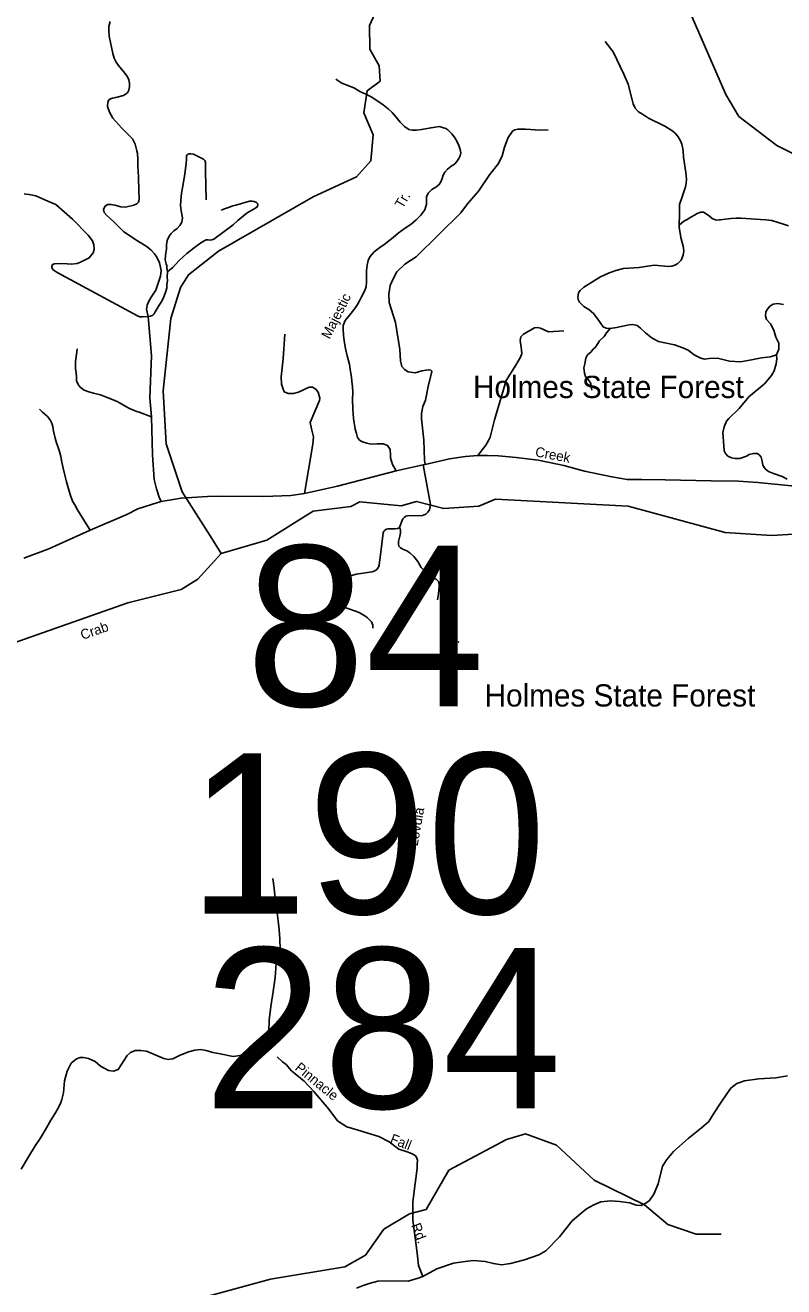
# Model space of a CAD drawing. Extents: x 884530 to 1028605, y 526725 to 653634.
# Drawn here: x 927736 to 932778, y 556470 to 564854 of the extents above; entities that cross this region are included whole.
import ezdxf

# ---------------------------------------------------------------- set-up
doc = ezdxf.new("R2010")
doc.units = 0
for name, color, linetype in [('Exist Boundary Land Use Park Urban CELL', 7, 'Continuous'), ('Exist Hydrographic Creek Single Shore', 7, 'Continuous'), ('Exist Hydrographic Creek Single Shore Label', 7, 'Continuous'), ('Exist Hydrographic Misc Water Feature', 7, 'Continuous'), ('Exist Road Non-System Type 51', 7, 'Continuous'), ('Exist Road Non-System Type 51 Label', 7, 'Continuous'), ('Exist Road Secondary Structure Standard Bridge Number Label', 7, 'Continuous'), ('Exist Road Secondary Type 51 Attributed', 7, 'Continuous'), ('Exist Road Secondary Type 51 Label', 7, 'Continuous')]:
    doc.layers.add(name, color=color, linetype=linetype)

msp = doc.modelspace()

# ---------------------------------------------------------------- linework, layer by layer
at = {"layer": 'Exist Hydrographic Creek Single Shore'}
for points in [[(929039.2, 561344.2), (928965.5, 561460), (928778.8, 561753.2), (928673.5, 562073.5), (928652.7, 562425.1), (928703.3, 562906.5), (928769.1, 563112), (928822.3, 563196.2), (929019.6, 563353), (929649.6, 563714.4), (929938, 563846.4), (930033.4, 563952.8), (930048, 564126.4), (929986.6, 564272.1), (930008.3, 564419.3), (930094.1, 564483.3), (930089.5, 564585.1), (930026.6, 564694.6), (930024.1, 564852.2), (930214.1, 565271.7)], [(929039.2, 561344.2), (929342.7, 561433.3), (929649.7, 561624.1), (929900.9, 561655.1), (929960.4, 561686.7), (930234.7, 561661.4), (930335.8, 561689), (930517.6, 561642.7), (930751.5, 561657.6), (930861.6, 561704.7), (931744, 561657.4), (932388.1, 561483.6), (932695.8, 561464.3), (933214.1, 561493.2)], [(925599.7, 560068.1), (925623, 560115.1), (925760.3, 560250.2), (925976.4, 560287.6), (926046.4, 560274.2), (926259.6, 560206.9), (926485.6, 560125.7), (926719.4, 560134.1), (926889.4, 560229.1), (927063, 560416), (927234.9, 560556.9), (927489.8, 560689.6), (928418.7, 561015.5), (928772, 561103.5), (928883, 561173.5), (929039.2, 561344.2)]]:
    msp.add_lwpolyline(points, dxfattribs=at)
at = {"layer": 'Exist Hydrographic Misc Water Feature'}
for points in [[(933885.2, 563471.6), (932730.5, 564056.1), (932479, 564248.2), (932392.5, 564394.3), (932130.4, 564993.6), (931996.2, 565206.3)], [(928389.9, 556031.3), (928498.1, 556025.8), (928757.7, 556283.1), (928903.5, 556395), (929366.5, 556520.3), (929861.4, 556602.1), (929997.7, 556681.5), (930120.6, 556852.9), (930291, 556954.5), (930400.6, 556985.1), (930551.5, 557244.6), (930934.1, 557450.2), (931060.6, 557487), (931266.4, 557410.7), (931516.4, 557179.2), (931852.5, 557015), (932006.2, 556883.9), (932195.9, 556821), (932362.6, 556820.9)]]:
    msp.add_lwpolyline(points, dxfattribs=at)
at = {"layer": 'Exist Road Non-System Type 51'}
msp.add_line((930382, 561933.2), (930202.2, 561892.7), dxfattribs=at)
for points in [[(928553.3, 562919.2), (928542.9, 562968.4), (928543.9, 562979.3), (928546.3, 562993.1), (928555.9, 563016.2), (928572.2, 563048), (928603.2, 563094.2), (928623.8, 563152.6), (928635.8, 563186.9), (928640, 563224.6), (928628.9, 563276.1), (928610.3, 563313.2), (928596.2, 563336.1), (928574, 563360.1), (928546.5, 563380.8), (928483.1, 563421.9), (928391.2, 563481.9), (928325, 563546.8), (928279.2, 563589.8), (928261.6, 563610.3), (928256.7, 563629.8), (928264.5, 563650.3), (928283.1, 563662), (928305.5, 563664), (928331.9, 563658.1), (928372, 563648.4), (928402.2, 563646.4), (928458.8, 563658.1), (928478.3, 563666.9), (928488.3, 563678.2), (928492.3, 563686.1), (928493.2, 563699.8), (928491, 563752.8), (928488, 563846.6), (928485.2, 563916.8), (928485.2, 563962.7), (928482.3, 564005.1), (928478.6, 564019.7), (928467.4, 564064.3), (928449.3, 564099.3), (928377.2, 564169.3), (928318.1, 564237.1), (928296.7, 564276.1), (928283.1, 564315.2), (928285.3, 564343.3), (928292.8, 564358.1), (928303.6, 564365.9), (928317.2, 564370.6), (928338.7, 564373.8), (928389.5, 564388.4), (928414.8, 564406), (928424.7, 564422.6), (928428.6, 564445), (928429.5, 564469.4), (928424.2, 564491.7), (928415.9, 564510.4), (928398.2, 564535.8), (928356.5, 564587.1), (928340.4, 564609.7), (928327, 564635.9), (928317.5, 564666), (928294, 564781.3), (928291.1, 564821.8), (928292.8, 564845.3), (928301.6, 564878.5)], [(932082.3, 563524.4), (932082.3, 563525.1), (932083.7, 563599.8), (932083.7, 563663.6), (932102.9, 563714.7), (932124.7, 563780.6), (932129.9, 563804.4), (932130.6, 563832.2), (932126.5, 563876.3), (932111.8, 563977.4), (932109.2, 564020.3), (932105.2, 564043.5), (932099.4, 564063.7), (932090.2, 564085.7), (932076.7, 564111.9), (932056.2, 564136.1), (932034, 564154.5), (931987.5, 564182.6), (931879.5, 564236.9), (931838.1, 564263), (931813.2, 564279.4), (931790.9, 564303.6), (931775.8, 564331.6), (931769.6, 564358.2), (931742.6, 564462.3), (931715.1, 564529.8), (931644.4, 564678.6), (931589.5, 564745.3)], [(930001, 564396.7), (929959.5, 564413.6), (929923.5, 564435.3), (929886.6, 564452.5), (929841.3, 564468.4), (929820.3, 564481.9), (929800.7, 564495.1)], [(930202.2, 561892.7), (930177.2, 561935.8), (930164.8, 561980.1), (930164.8, 562009.7), (930162.3, 562022), (930162.3, 562034.3), (930144.2, 562060.3), (930114.4, 562073.2), (930075, 562072.6), (930034.5, 562071), (930005.8, 562076.7), (929978.7, 562086.7), (929957.4, 562097.7), (929944.5, 562113.6), (929938.2, 562140.4), (929928.2, 562170.7), (929917.6, 562241.4), (929913.7, 562302.5), (929910.8, 562367.4), (929913.7, 562415.6), (929910.4, 562454.2), (929907.8, 562486), (929904.5, 562516.6), (929898.7, 562553.9), (929890.3, 562598.7), (929876.5, 562657.9), (929864.3, 562706.1), (929855.4, 562757.1), (929852.1, 562795.3), (929850.3, 562832.1), (929849.1, 562859.5), (929861.9, 562891.4), (929893.1, 562930.8), (929927.4, 562972.6), (929944.8, 562997.8), (929958.8, 563022.2), (929972.2, 563048.6), (929984.4, 563073.7), (929995.5, 563098.2), (930002.7, 563117.8), (930004.7, 563145), (930003.4, 563181.2), (930005, 563224.5), (930009.5, 563260.5), (930015.9, 563289.8), (930027.4, 563314.9), (930056, 563347.6), (930092.6, 563376.9), (930128.1, 563402.4), (930153.8, 563422.3), (930180.8, 563444.6), (930215.7, 563472.8), (930262.7, 563507.5), (930300.2, 563533.4), (930335.2, 563560.7), (930365.8, 563591.1), (930391.1, 563626.9), (930403.2, 563665.5), (930402.7, 563689.3), (930403.3, 563714), (930413.2, 563739.4), (930438.2, 563763.6), (930465.5, 563778.4), (930488.4, 563795.4), (930499.4, 563814.4), (930507.3, 563836.6), (930514.4, 563858.2), (930525.4, 563878.9), (930542, 563897.4), (930564.4, 563915), (930574.6, 563921.7), (930583.5, 563927.3), (930591.6, 563933.4), (930605.6, 563949.2), (930617.2, 563968.2), (930625.9, 563986.9), (930630.3, 564006.4), (930627.6, 564028.5), (930617.5, 564054.9), (930601.5, 564087.8), (930587.8, 564112.2), (930571.6, 564133.7), (930559.3, 564146.6), (930545.6, 564159), (930531.9, 564169.2), (930487.4, 564180.8), (930434, 564172.9), (930370.4, 564161.7), (930337.6, 564158), (930309.9, 564157), (930286, 564161.7), (930256.6, 564180.9), (930229.2, 564210.7), (930201.7, 564244.4), (930175.5, 564274.4), (930149.2, 564299.7), (930114.6, 564326), (930072.6, 564354.8), (930036.2, 564378.1), (930001, 564396.7)], [(930393.2, 561935.4), (930389.8, 561963.4), (930386.1, 562096.3), (930369.2, 562238.7), (930370.4, 562274.7), (930378.2, 562319.6), (930396.8, 562362.6), (930413.5, 562452.9), (930438.8, 562552.1), (930436.4, 562558.3), (930431.1, 562561.8), (930416.3, 562564.1), (930372.8, 562556.6), (930328.3, 562543.7), (930281.7, 562550.4), (930257.5, 562565.9), (930239.1, 562587.3), (930229.4, 562623.1), (930226.6, 562698.6), (930196.9, 562877.9), (930154.9, 563011.9), (930152.5, 563066.1), (930162.4, 563125.2), (930182.1, 563169.5), (930206.7, 563216.3), (930258.4, 563265.6), (930334.7, 563316.1), (930630.2, 563607.9), (930674.6, 563667), (930748.4, 563750.8), (930822.3, 563859.1), (930881.4, 563935.4), (930906.1, 563987.1), (930920.8, 564043.7), (930945.5, 564107.8), (930975, 564149.7), (930991.2, 564158.4), (931010, 564162.8), (931028.5, 564162.9), (931060.7, 564164.5), (931159.5, 564156.5), (931212.7, 564159.3)], [(928680.8, 563214.6), (928680.3, 563229.3), (928677.7, 563244.4), (928676.2, 563255.3), (928673, 563267.9), (928666.7, 563296.1), (928668.3, 563324.1), (928675.1, 563367.9), (928675.1, 563394.4), (928678.6, 563423.6), (928692.4, 563453.6), (928706.1, 563470), (928723.2, 563487.9), (928745.5, 563502.6), (928764.3, 563524), (928776.4, 563545.5), (928780.6, 563573.8), (928772.1, 563620), (928768.6, 563657), (928769.6, 563688.7), (928775.5, 563739.3), (928785.8, 563798.4), (928797.9, 563867.1), (928803.8, 563917.4), (928808.8, 563959.8), (928808.1, 563976), (928808.1, 563987.2), (928815, 563995.8), (928826.2, 563999.2), (928837.3, 564000.1), (928853.6, 563997.4), (928903.4, 563972.6), (928921.4, 563963.2), (928929.1, 563956.3), (928934.2, 563945.1), (928934.3, 563934), (928935, 563884.3), (928939.4, 563693.8)], [(928553.3, 562919.2), (928514.8, 562916.8), (928498.5, 562917.5), (928482, 562923), (928005.2, 563180.3), (927952.2, 563208.6), (927925, 563226.2), (927916, 563236.6), (927912.9, 563244.2), (927912.7, 563251), (927914.4, 563258.1), (927917.9, 563263.9), (927923.8, 563267.6), (927930.3, 563269), (927986.4, 563269.9), (928044.2, 563266.4), (928082, 563271.1), (928104.4, 563280.6), (928161.1, 563308.9), (928188.1, 563341.9), (928195.2, 563363.2), (928193, 563395), (928182.3, 563422.2), (928155.1, 563458.8), (928051.3, 563566.1), (927940.3, 563662.9), (927886.1, 563684.1), (927845.9, 563703), (927807, 563720.7), (927762.7, 563729.2), (927739.8, 563731.3), (927728, 563732.9)], [(928680.8, 563214.6), (928696.5, 563228.8), (928716.4, 563243.5), (928736, 563263.3), (928761.8, 563294.1), (928785.8, 563315.5), (928810.7, 563337.9), (928862.2, 563378.2), (928909.4, 563412.5), (928938.5, 563427.9), (928951.3, 563427.9), (928966.8, 563426.2), (928975.4, 563428.7), (928989.1, 563433), (929117.9, 563527.4), (929149.5, 563557.5), (929210.4, 563608.1), (929262.7, 563636.4), (929278.2, 563646.6), (929282.5, 563657.8), (929280.8, 563669.8), (929272.2, 563676.7), (929257.6, 563682.7), (929243, 563686.1), (929227.6, 563686.1), (929135.8, 563659.5), (929116.1, 563654.4), (929086.1, 563644), (929061.2, 563633.7), (929038.9, 563624.3)], [(932082.3, 563525.1), (932082.3, 563525.1), (932099.1, 563540.1), (932114, 563551.2), (932134.5, 563562.7), (932160.8, 563579.2), (932184.6, 563591.5), (932203.1, 563603.1), (932225.7, 563611.3), (932234.6, 563613.1), (932243.2, 563611.5), (932262.4, 563600.6), (932284.8, 563584.6), (932302, 563570.2), (932317.2, 563563), (932333.4, 563559.6), (932348.5, 563560.4), (932358.2, 563561.5), (932388.3, 563565.1), (932428.1, 563569.6), (932460.4, 563572.5), (932494.6, 563572.7), (932528.5, 563570.4), (932560.4, 563567.2), (932590.6, 563564.7), (932623.1, 563563.8), (932657.7, 563561.9), (932698.2, 563555.6), (932740.6, 563543.9), (932775.3, 563531.7), (932808.6, 563521.6)], [(931623.3, 562838.1), (931598.2, 562840.1), (931577.8, 562850.7), (931561.1, 562871.8), (931541.5, 562901.4), (931513.9, 562937.9), (931481.9, 562964.5), (931448.8, 562986.1), (931420.3, 563013.9), (931410.5, 563032.4), (931408.6, 563045.5), (931410.5, 563059.5), (931414, 563075.6), (931425.4, 563091.7), (931449.6, 563113.4), (931560.3, 563181.8), (931612.6, 563206.2), (931662, 563223.6), (931713.4, 563238.2), (931816, 563244), (931916.8, 563259.5), (932010.7, 563251.1), (932034.3, 563252.8), (932053.5, 563259.5), (932072.8, 563271.8), (932096.5, 563293.5), (932109.3, 563325.4), (932112.4, 563354), (932109.3, 563386), (932093, 563443.7), (932082.4, 563513.4), (932082.3, 563524.4)], [(928553.3, 562919.2), (928567.9, 562921.6), (928583.5, 562927.4), (928592.5, 562936.4), (928599.9, 562948.7), (928613.8, 562972.5), (928626, 562994), (928639.3, 563013.5), (928652.6, 563037.8), (928658.8, 563056.6), (928669.8, 563084.8), (928676.2, 563110.3), (928677.9, 563131.7), (928680.8, 563156.7), (928679.2, 563181.8), (928680.8, 563214.6)], [(932728.9, 562663.9), (932744, 562702.5), (932744.6, 562740.9), (932724.8, 562780.5), (932712.4, 562827.4), (932688.6, 562869.9), (932663.6, 562899.1), (932655.9, 562923.4), (932658.8, 562949.5), (932670.4, 562967), (932684.8, 562987.3), (932708.1, 562999.9), (932735.3, 563004.7), (932775, 562998.9)], [(928575.3, 562251.5), (928565.4, 562378.2), (928576.4, 562656.3), (928553.3, 562919.2)], [(930743.6, 561995), (930796.6, 562064.4), (930815.8, 562093.8), (930827.1, 562116.9), (930854.3, 562231.3), (930932.8, 562493.5), (930997.9, 562594.2), (931027.5, 562648.9), (931036.4, 562672.6), (931035.1, 562698.1), (931025.7, 562759.9), (931030.5, 562783.6), (931048.7, 562801.9), (931121.5, 562843), (931138.5, 562845.8), (931161.3, 562841), (931214.3, 562817.6), (931316.8, 562823.4)], [(931623.3, 562838.1), (931599.1, 562809.1), (931584.5, 562786.8), (931553.7, 562756), (931538.2, 562733.5), (931526.7, 562715.1), (931511.8, 562701.3), (931494.5, 562681.6), (931473.4, 562662.9), (931462.4, 562642.1), (931455, 562605), (931449.6, 562576.5), (931452.5, 562543.2), (931460, 562521), (931484.7, 562491.3), (931494.5, 562474.1), (931497, 562451.8), (931501.9, 562429.6)], [(932728.9, 562663.9), (932688.8, 562651.1), (932629.7, 562644.4), (932562.8, 562631.8), (932490.1, 562618.3), (932416, 562622.3), (932336.1, 562642.5), (932281.9, 562638.6), (932250.9, 562634.7), (932225.7, 562642.5), (932181.2, 562664.8), (932142.5, 562694.8), (932106, 562710.8), (932050.6, 562731.2), (931944.1, 562753.2), (931903.3, 562774.2), (931857.7, 562810), (931825.8, 562841), (931802.5, 562859.5), (931773.5, 562866.2), (931751.2, 562862.3), (931665, 562844.6), (931623.3, 562838.1)], [(929593.3, 561742.6), (929648.3, 562070), (929652.2, 562118.5), (929637.7, 562171.7), (929630.9, 562213.9), (929691.9, 562360.9), (929694.8, 562376.9), (929684.1, 562416.8), (929668.6, 562435.2), (929644.4, 562448.7), (929623.1, 562449.7), (929552.2, 562415.5), (929519.2, 562406.2), (929484.2, 562406.5), (929458, 562418.5), (929447.3, 562442.1), (929439.1, 562470.1), (929438.1, 562518.5), (929449.7, 562637.6), (929461.4, 562800.4)], [(928575.3, 562251.5), (928492.6, 562282.2), (928477.3, 562287), (928454.9, 562296.4), (928430.1, 562307), (928404.2, 562321.1), (928351, 562351.5), (928320.4, 562364.8), (928280.9, 562379.4), (928235.7, 562397.3), (928189.2, 562409.2), (928159.6, 562417.6), (928127.3, 562428.8), (928100.6, 562449.9), (928088, 562466.8), (928078, 562492.1), (928076.7, 562514.7), (928073.8, 562544.2), (928071.1, 562572.3), (928069.6, 562597.6), (928071.1, 562620.2), (928079.5, 562683.4), (928082.3, 562704.5)], [(932801.1, 561837.6), (932766.2, 561855), (932710.2, 561874.5), (932676.2, 561888.9), (932654.9, 561907.2), (932639.2, 561931.2), (932634.6, 561956.7), (932626.8, 561982.8), (932616.1, 561996.4), (932602.6, 562008), (932577.4, 562009), (932547.3, 562002.2), (932528.9, 561990.6), (932486.3, 561974.1), (932455.3, 561975.1), (932429.2, 561978.9), (932406.9, 561991.6), (932389.5, 562008), (932381.8, 562026.4), (932379, 562060), (932372.6, 562146.9), (932381.1, 562185), (932397.9, 562222.8), (932412.1, 562241), (932480.2, 562308.2), (932545.8, 562384), (932649.4, 562471.8), (932696.5, 562527.7), (932712.9, 562557), (932727.5, 562604.6), (932731.6, 562638.3), (932728.9, 562663.9)], [(928166.7, 561499.5), (928118.8, 561576.4), (928083.7, 561634.1), (928066.9, 561667.9), (928051.4, 561691.8), (928034.5, 561735.4), (928024.6, 561773.3), (928010.6, 561819.8), (927999.3, 561864.8), (927988, 561909.8), (927979.6, 561950.6), (927972.5, 561987.2), (927964.1, 562022.4), (927955.7, 562049), (927944.4, 562080), (927936, 562110.9), (927923.4, 562157.4), (927919.1, 562188.3), (927910.7, 562213.6), (927903.6, 562227.7), (927893.8, 562243.2), (927881.1, 562257.3), (927867, 562269.9), (927850.2, 562282.5), (927830.5, 562303.7)], [(928639.7, 561689.3), (928626, 561717), (928609.5, 561772.4), (928592.9, 561834.9), (928581.1, 562000.2), (928575.3, 562251.5)], [(930382, 561933.2), (930430.6, 561669.4), (930428.4, 561652.9), (930423.5, 561633.8), (930413, 561617.7), (930398.1, 561604.1), (930377.1, 561595.4), (930277.2, 561592.9), (930266, 561591.1), (930255, 561583.6), (930245.6, 561573.1), (930238.8, 561558.2), (930222.7, 561517.3)], [(930222.7, 561517.3), (930218, 561512.8), (930210.3, 561510.4), (930192.9, 561508.6), (930145.6, 561506.7), (930137.2, 561505.5), (930126, 561499.3), (930119.2, 561492.5), (930114.9, 561481.3), (930098.1, 561333.8), (930089.2, 561268.2), (930083.9, 561252), (930073.9, 561237.8), (930059.7, 561227.8), (930041.1, 561221.2), (929936.3, 561206.1), (929914, 561198.7), (929899.7, 561194.4), (929880.5, 561184.4), (929864.4, 561172.1), (929849.6, 561155.3), (929844.7, 561141), (929840.9, 561112.6), (929835.9, 561031.3), (929837.8, 561015.3), (929842.1, 561000.9), (929855.1, 560986.7), (929955, 560950.7), (929989.9, 560931.6), (929999, 560924.1), (930010.5, 560915.8), (930037.3, 560889.3), (930042.9, 560878.9), (930046.1, 560866.5), (930045.4, 560847.2)], [(930222.7, 561517.3), (930228.4, 561507.8), (930230.2, 561501), (930230.2, 561494.4), (930229.5, 561480.1), (930226.5, 561459), (930217.8, 561423.1), (930216.5, 561405.1), (930220.2, 561392.7), (930231.4, 561380.9), (930251.2, 561371), (930272.3, 561361), (930291.5, 561347.5), (930318.7, 561323.9), (930344.8, 561289.8), (930366.9, 561250.2), (930398.4, 561216.3), (930438.4, 561184.8), (930467.4, 561172.7), (930482, 561158.2), (930488, 561141.2), (930488, 561121.9), (930482, 561075.9), (930475.9, 561034.7)], [(927710.2, 557251.9), (927758.4, 557333.4), (927802.7, 557406.2), (927836.3, 557456.5), (927868.5, 557511.8), (927905.7, 557577.1), (927932.3, 557620.1), (927955.2, 557656.4), (927973.8, 557695.2), (927978.7, 557714.8), (927989.9, 557759), (927996.2, 557838.6), (928015, 557904.1), (928041.7, 557956.3), (928077.7, 557984.3), (928101.8, 557993.6), (928123.1, 557995), (928157.5, 557988.6), (928200.6, 557967.3), (928237.1, 557936.8), (928288.9, 557906.7), (928323.7, 557902.7), (928354.4, 557914.8), (928413.3, 558008.4), (928436, 558027), (928466.7, 558040.4), (928505.5, 558041.8), (928542.9, 558036.4), (928599, 558011), (928656.5, 557987), (928685.9, 557981.6), (928716.7, 557985.6), (928762.1, 558007), (928820.8, 558032.4), (928862.4, 558043.1), (928903.8, 558047.1), (928938.5, 558040.4), (928984, 558027), (929032, 558017.7), (929117.6, 558001.1), (929165.7, 558008.4), (929223.1, 558024.4), (929261.9, 558041.8), (929294.1, 558053.8), (929323.4, 558076.5), (929339.5, 558092.6), (929350.2, 558115.3), (929354.2, 558167.4), (929358.2, 558242.3), (929367.6, 558333.1), (929383.6, 558432.1), (929396.9, 558526.9), (929403.6, 558619.2), (929431.3, 558710.9), (929428, 558783.2), (929423.1, 558841.6), (929416.2, 558903.5), (929407.6, 558973.8), (929398.1, 559051.5), (929389.8, 559119.9), (929382, 559183.5)], [(930378.9, 556538.6), (930350.4, 556610.8), (930344, 556672.8), (930334.1, 556747.8), (930311.4, 556914.2), (930311.4, 557031.7), (930324.4, 557123.1), (930337.4, 557224.3), (930340.7, 557260.1), (930340.7, 557286.2), (930344, 557312.4), (930337.4, 557331.9), (930327.7, 557341.8), (930308.1, 557354.7), (930281.9, 557364.6), (930219.9, 557384.1), (930154.7, 557433.1), (930086.1, 557469), (930014.3, 557491.8), (929949.1, 557511.4), (929874.1, 557534.3), (929812.1, 557573.4), (929753.3, 557651.8), (929655.4, 557769.2), (929590.1, 557837.7), (929505.3, 557906.3), (929469.4, 557948.7), (929446.5, 557965), (929410.7, 557997.6)]]:
    msp.add_lwpolyline(points, dxfattribs=at)
at = {"layer": 'Exist Road Secondary Type 51 Attributed'}
for points in [[(927727.5, 561312.7), (927893.8, 561374.7), (928166.7, 561499.5), (928412.3, 561602.3), (928483.7, 561639.9), (928574.3, 561669), (928639.7, 561689.3), (928772.4, 561711.7), (928947, 561723), (929020.1, 561724.1), (929323, 561723.4), (929501.4, 561729.7), (929593.3, 561742.6), (929812.7, 561791.9), (930202.2, 561892.7), (930382, 561933.2), (930393.2, 561935.4), (930555.5, 561972.5), (930663.3, 561989.2), (930743.6, 561995), (930808.3, 561994.7), (930881.8, 561992.2), (930998.4, 561981.7), (931144.6, 561964.2), (931315.5, 561928.6), (931452.6, 561891.8), (931636, 561853), (931736.7, 561835.8), (931834.4, 561835.8), (931989.8, 561832.5), (932294, 561826.6), (932477, 561823.3), (932605.3, 561814.5), (932851.5, 561790.1)], [(930378.9, 556538.6), (930471.6, 556589.1), (930582.7, 556628.4), (930659.6, 556639.3), (930716.4, 556644.3), (930793.3, 556637.6), (930848.4, 556624.2), (930900.6, 556616.3), (930962.5, 556625.5), (931054.4, 556649.7), (931149.2, 556682.7), (931196.9, 556710.3), (931286.3, 556801.5), (931372.3, 556908.5), (931428.3, 556956.9), (931467.6, 556988.7), (931515.2, 557015.5), (931562, 557033.9), (931627.2, 557042.2), (931685.7, 557038), (931755, 557028), (931797.2, 557012.5), (931829.8, 557010.9), (931859.9, 557025.1), (931885, 557044.3), (931913.4, 557085.3), (931941.8, 557154.7), (931972.3, 557271.3), (932001.5, 557316.4), (932045.8, 557369.1), (932143.2, 557455.6), (932230.9, 557527.5), (932280.2, 557569.3), (932315.7, 557625.7), (932357.5, 557691), (932399.7, 557752.4), (932425.6, 557790.9), (932466.6, 557821), (932516.7, 557840.2), (932612.2, 557852.6), (932723.9, 557859.4), (932802, 557873.2)], [(929937.6, 556460.4), (929981.9, 556478.8), (930021.2, 556491.3), (930078.8, 556508), (930138.2, 556509.7), (930281, 556507.2), (930347.9, 556528.1), (930378.9, 556538.6)]]:
    msp.add_lwpolyline(points, dxfattribs=at)

# ---------------------------------------------------------------- texts
at = {"layer": 'Exist Boundary Land Use Park Urban CELL'}
for p in [(930712.1, 562376.8), (930789.2, 560326.6)]:
    msp.add_text('Holmes State Forest', height=147.638, dxfattribs=at).set_placement(p)
at = {"layer": 'Exist Hydrographic Creek Single Shore Label'}
msp.add_text('Crab', height=65.62, rotation=19.32948, dxfattribs=at).set_placement((928116.8, 560768.7))
msp.add_text('Crab', height=65.62, rotation=19.32948, dxfattribs=at).set_placement((928116.8, 560768.7))
at = {"layer": 'Exist Road Non-System Type 51 Label'}
for s, rotation, p in [('Tr.', 59.78951, (930244.7, 563631.7)), ('Majestic', 63.23066, (929758.7, 562764.2)), ('Ln.', 39.49596, (930534.8, 560681.3)), ('Lovdia', 79.97182, (930343.8, 559395.5)), ('Pinnacle', 320.69453, (929523.7, 557916.8)), ('Fall', 338.40096, (930155.5, 557428.4)), ('Rd.', 291.32923, (930299.6, 556878.8))]:
    msp.add_text(s, height=65.62, rotation=rotation, dxfattribs=at).set_placement(p)
at = {"layer": 'Exist Road Secondary Structure Standard Bridge Number Label'}
for s, p in [('84', (929203.3, 560328.7)), ('190', (928819.3, 558949.4)), ('284', (928922.5, 557656.5))]:
    msp.add_text(s, height=1066.27, dxfattribs=at).set_placement(p)
at = {"layer": 'Exist Road Secondary Type 51 Label'}
msp.add_text('Creek', height=65.62, rotation=349.42629, dxfattribs=at).set_placement((931121.9, 561989.7))

doc.saveas('drawing.dxf')
